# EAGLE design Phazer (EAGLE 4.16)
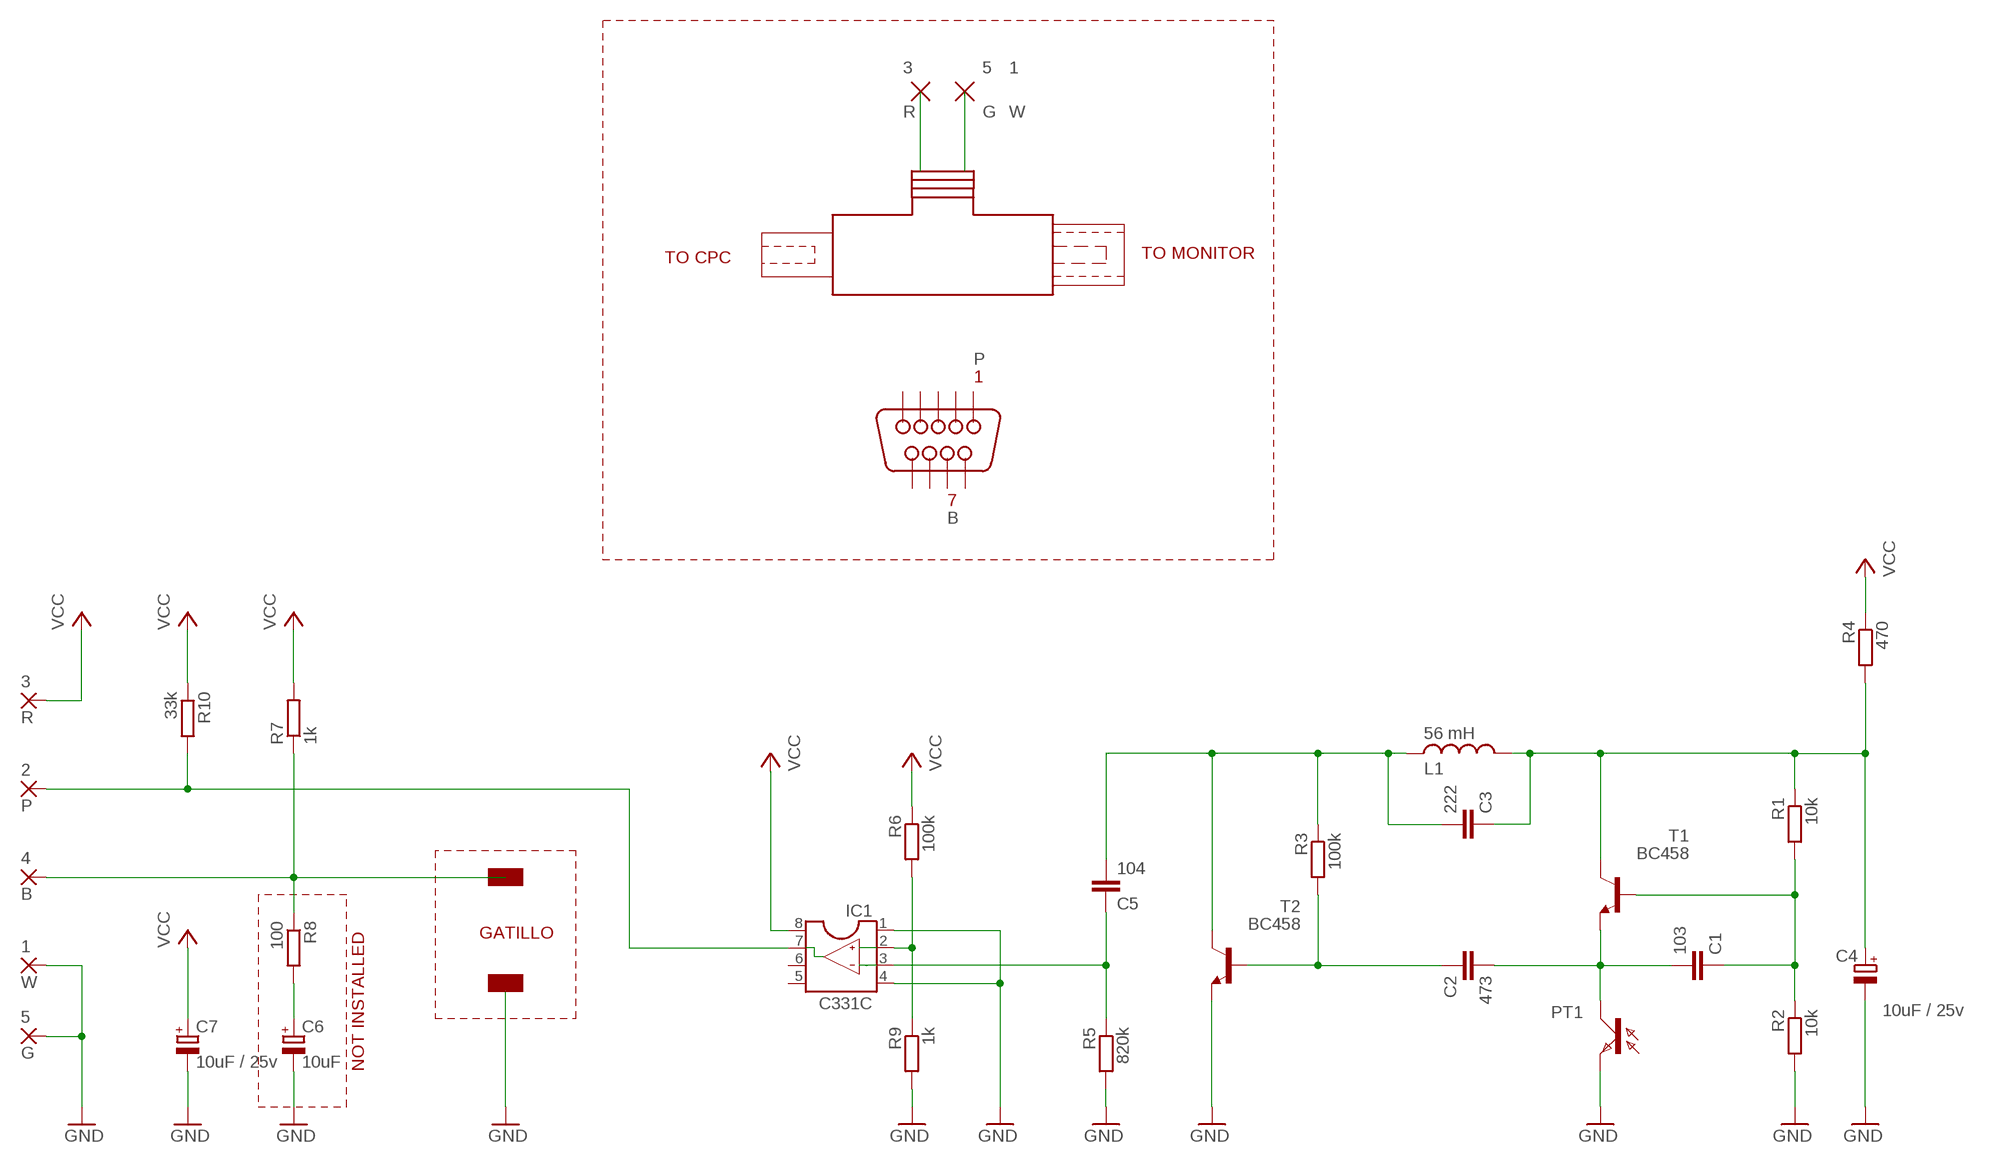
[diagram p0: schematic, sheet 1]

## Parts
1  W  SMD2  [SMD1,27-2,54]
2  P  SMD2  [SMD1,27-2,54]
3  R  SMD2  [SMD1,27-2,54]
4  B  SMD2  [SMD1,27-2,54]
5  G  SMD2  [SMD1,27-2,54]
C1  103  C-EU050-024X044  [C050-024X044]
C2  473  C-EU050-024X044  [C050-024X044]
C3  222  C-EU050-024X044  [C050-024X044]
C4  10uF / 25v  CPOL-EUE5-5  [E5-5]
C5  104  C-EU050-024X044  [C050-024X044]
C6  10uF  CPOL-EUE5-5  [E5-5]
C7  10uF / 25v  CPOL-EUE5-5  [E5-5]
IC1  C331C  DIL8  [DIL08]
L1  56 mH  L-US0204/5  [0204/5]
PT1  LPT80A  [LPT80A]
R1  10k  R-EU_0207/10  [0207/10]
R2  10k  R-EU_0207/10  [0207/10]
R3  100k  R-EU_0207/10  [0207/10]
R4  470  R-EU_0207/10  [0207/10]
R5  820k  R-EU_0207/10  [0207/10]
R6  100k  R-EU_0207/10  [0207/10]
R7  1k  R-EU_0207/10  [0207/10]
R8  100  R-EU_0207/10  [0207/10]
R9  1k  R-EU_0207/10  [0207/10]
R10  33k  R-EU_0207/10  [0207/10]
T1  BC458  BC368-NPN-TO92-BCE  [TO92-BCE]
T2  BC458  BC368-NPN-TO92-BCE  [TO92-BCE]

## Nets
GND: 1.1(P) 5.1(P) C4.- C6.- C7.- IC1.1 IC1.4 PT1.E R2.2 R5.2 R9.2 T2.E
N$1: C1.2 C2.2 PT1.C T1.E
N$2: C2.1 R3.2 T2.B
N$3: C1.1 R1.2 R2.1 T1.B
N$4: C3.1 C4.+ L1.1 R1.1 R4.2 T1.C
N$5: C3.2 C5.2 L1.2 R3.1 T2.C
N$6: 2.1(P) IC1.7 R10.2
N$7: C5.1 IC1.3 R5.1
N$8: C6.+ R8.2
N$12: IC1.2 R6.2 R9.1
N$13: 4.1(P) R7.1 R8.1
VCC: 3.1(P) C7.+ IC1.8 R4.1 R6.1 R7.2 R10.1
Unconnected: IC1.5 IC1.6

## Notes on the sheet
- 3 | 5 | 1
- R | G | W
- TO CPC | TO MONITOR
- P
- 1
- 7
- B
- GATILLO
- NOT INSTALLED

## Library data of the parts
1-5 = wirepad:SMD2: SMD PAD
C1-C3 C5 = rcl:C-EU: CAPACITOR, European symbol
C4 C6 C7 = rcl:CPOL-EU: POLARIZED CAPACITOR, European symbol
IC1 = ic-package:DIL8: Dual In Line
L1 = rcl:L-US: INDUCTOR, American symbol
PT1 = opto-trans-siemens:LPT80A: PHOTO TRANSISTOR
R1-R10 = rcl:R-EU_: RESISTOR, European symbol
T1 T2 = transistor:*-NPN-: NPN Transistror

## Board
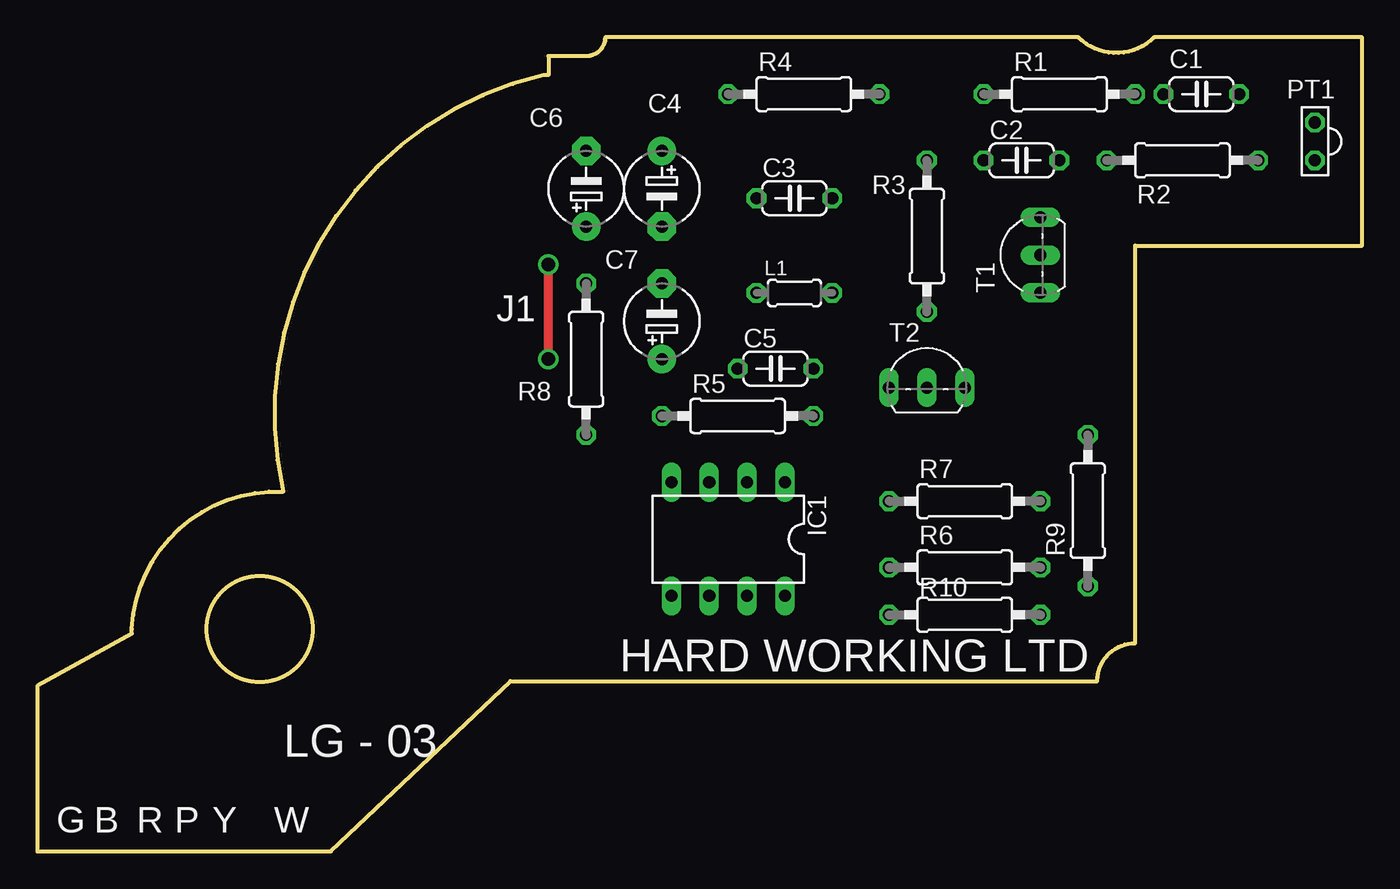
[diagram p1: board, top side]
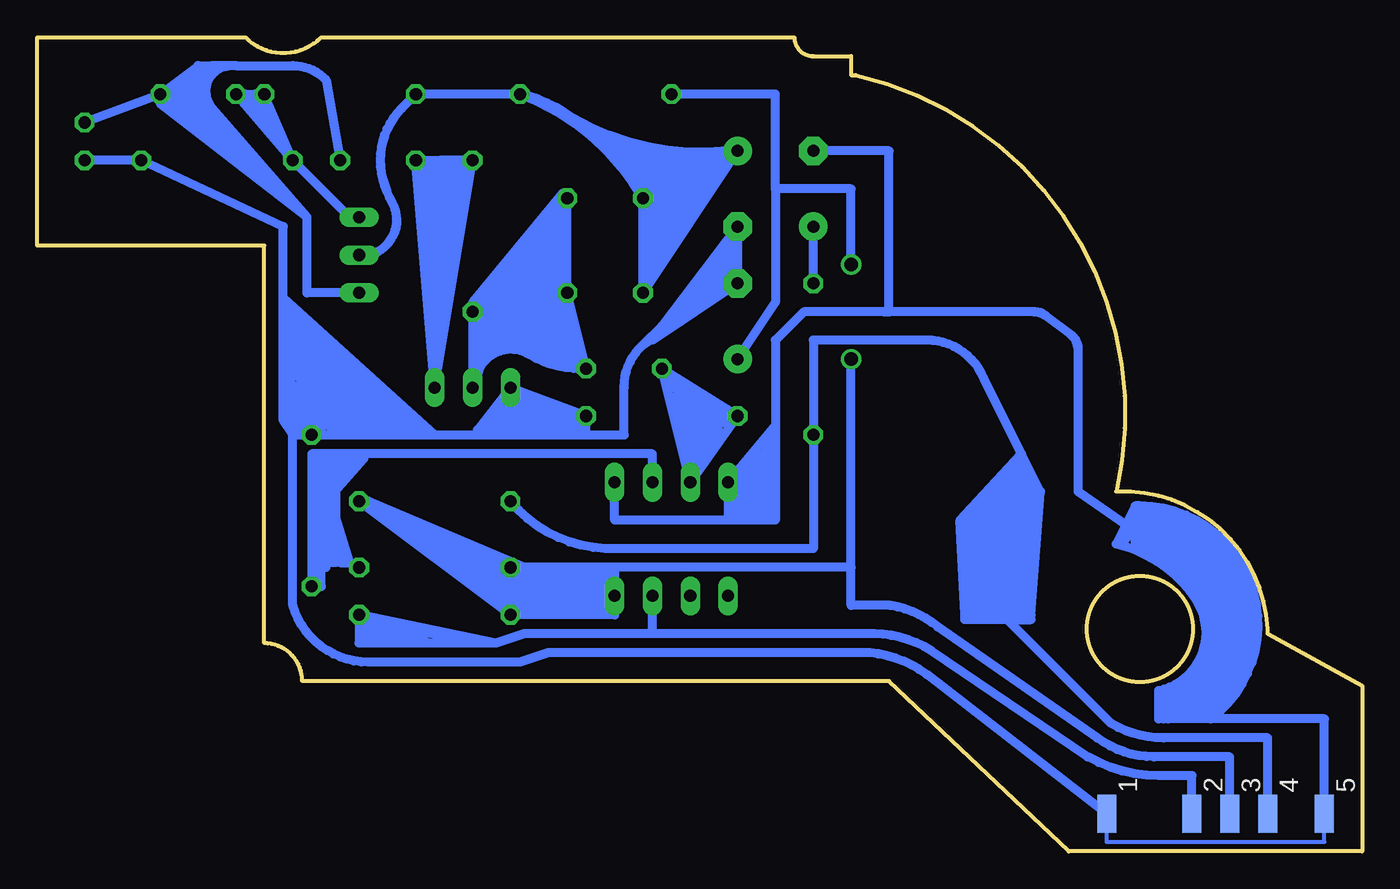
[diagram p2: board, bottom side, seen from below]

Size 88.9 x 54.61 mm. Coordinates in mm from the lower left corner, seen from the top.
Outline: 74.93,54.61 arc-90 69.85,54.61 38.1,54.61 arc-90 36.83,53.34 34.29,53.34 34.29,52.07 33.97,52.07 arc90 16.51,24.13 arc90 6.35,14.92 6.35,14.61 0,11.11 0,0 19.68,0 31.75,11.43 71.12,11.43 arc-90 73.66,13.97 73.66,40.64 88.9,40.64 88.9,54.61 74.93,54.61
Outline: circle at 14.92,14.92 radius 3.55
Copper layers (1*16): Top 0.035mm / dielectric 1.5mm / Bottom 0.035mm
Design rules "default": minimum track width 10mil, minimum drill 24mil, track to track 8mil, track to pad 8mil, pad to pad 8mil, via to via 8mil, smd to smd 8mil, copper to edge 40mil, drill to drill 8mil, minimum pad ring 10mil, minimum via ring 8mil, stop-mask expansion 4mil, vias tented up to drill 0mil, thermal gap 10mil

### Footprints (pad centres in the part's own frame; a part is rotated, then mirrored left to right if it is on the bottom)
SMD1,27-2,54 = smd 1.27 x 2.54: 1 0,0
C050-024X044 = drill 0.813 octagon: 1 -2.54,0; 2 2.54,0
E5-5 = drill 0.813 pad 1.905 round: + -2.54,0 | drill 0.813 pad 1.905 octagon: - 2.54,0
DIL08 = drill 0.813 long: 1 -3.81,-3.81; 2 -1.27,-3.81; 3 1.27,-3.81; 4 3.81,-3.81; 5 3.81,3.81; 6 1.27,3.81; 7 -1.27,3.81; 8 -3.81,3.81
0204/5 = drill 0.813 octagon: 1 -2.54,0; 2 2.54,0
LPT80A = drill 0.813 octagon: C 0,-1.27; E 0,1.27
0207/10 = drill 0.813 octagon: 1 -5.08,0; 2 5.08,0
TO92-BCE = drill 0.813 long: B 2.54,0; C 0,0; E -2.54,0

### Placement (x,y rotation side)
1  17.14,2.54 180 bottom
2  11.43,2.54 180 bottom
3  8.89,2.54 180 bottom
4  6.35,2.54 180 bottom
5  2.54,2.54 180 bottom
C1  78.11,50.8 0 top
C2  66.04,46.35 0 top
C3  50.8,43.81 0 top
C4  41.91,44.45 270 top
C5  49.53,32.38 0 top
C6  36.83,44.45 90 top
C7  41.91,35.56 90 top
IC1  46.35,20.95 180 top
L1  50.8,37.47 0 top
PT1  85.72,47.62 180 top
R1  68.58,50.8 0 top
R2  76.83,46.35 0 top
R3  59.69,41.27 90 top
R4  51.44,50.8 0 top
R5  46.99,29.21 0 top
R6  62.23,19.05 0 top
R7  62.23,23.5 0 top
R8  36.83,33.02 90 top
R9  70.48,22.86 90 top
R10  62.23,15.88 0 top
T1  67.31,40.01 90 top
T2  59.69,31.11 0 top

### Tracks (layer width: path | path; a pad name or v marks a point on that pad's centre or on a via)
GND
  Bottom 0.254: 5.1 2.54,0.64 17.14,0.64 1.1
  Bottom 0.61: PT1.E R2.2 72.39,41.91 72.39,37.15 | 1.1 29.22,11.88 arc-32 33.06,13.34 54.61,13.34 56.52,12.7 66.67,12.7 arc74 71.75,16.51 71.75,27.94 | 71.75,27.94 72.39,28.89 72.39,31.75 | 72.39,31.75 72.39,37.15 | 71.75,27.94 R9.2 68.58,27.94 | 68.58,27.94 62.23,27.94 | 62.23,27.94 52.07,27.94 | 52.07,27.94 52.07,28.89 | 52.07,28.89 R5.2 | 52.07,27.94 49.53,27.94 49.53,31.11 arc48 48.26,33.97 | 48.26,33.97 46.99,35.24 C4.- | 48.26,33.97 47.31,34.61 | R5.2 T2.E 59.37,28.26 52.39,28.26 52.39,28.57 58.74,28.57 58.42,28.89 52.07,28.89 | 52.07,28.89 53.02,29.21 58.42,29.21 57.78,29.53 53.98,29.53 54.93,29.84 57.78,29.84 57.47,30.16 55.56,30.16 57.15,30.48 R5.2 | 72.39,37.15 62.23,27.94 | 72.39,37.15 63.18,28.26 72.07,36.2 63.5,28.26 72.07,35.56 64.14,28.26 72.07,34.92 64.77,28.26 72.07,34.29 65.41,28.26 72.07,33.66 66.04,28.26 72.07,33.02 66.67,28.26 72.07,32.38 67.31,28.26 72.39,31.75 | 72.39,31.75 67.94,28.26 72.07,31.11 68.58,27.94 | 68.58,27.94 72.07,30.48 69.85,28.26 72.07,31.75 72.07,28.57 71.44,28.26 70.8,28.26 | 70.8,28.26 70.48,28.26 71.75,29.53 71.75,28.89 70.8,28.26 | C4.- C7.- 47.62,34.29 | C4.- 46.67,35.24 42.23,39.69 45.72,35.56 42.23,39.05 43.81,37.15 42.23,38.42 | C6.- 31.75,46.99 31.75,36.2 32.07,36.2 | 32.07,36.2 37.47,36.2 39.37,34.29 39.37,28.57 | 39.37,28.57 39.37,22.23 50.16,22.23 IC1.1 | 39.37,28.57 IC1.4 42.55,22.54 39.69,22.54 39.69,27.62 40.01,27.3 40.01,22.86 42.23,22.86 42.23,24.77 40.32,26.67 40.32,23.18 41.91,23.18 41.91,24.77 40.64,25.72 40.64,23.5 40.96,23.5 40.96,25.08 41.59,24.77 41.59,23.5 | 5.1 2.54,8.89 10.16,8.89 | 10.16,8.89 13.02,8.89
  Bottom 0.61: 13.02,8.89 13.34,8.89 | 13.34,8.89 13.65,8.89 13.65,10.79 arc-111 11.11,16.83 arc-44 16.51,20.64 15.88,21.91 | 15.88,21.91 15.24,23.18 14.92,23.18 arc143 10.16,8.89 | 32.07,36.2 22.01,36.2 arc37 21.25,35.94 19.56,34.67 arc53 19.05,33.66 19.05,24.13 15.88,21.91 | 13.34,8.89 13.34,10.48 12.7,10.79 13.02,8.89 | 13.02,8.89 12.38,10.79 12.38,9.21 12.06,11.11 12.06,9.21 11.75,11.43 11.75,9.21 11.43,11.75 11.43,9.21 11.11,12.38 11.11,9.21 10.79,13.02 10.79,9.21 10.48,13.02 | 10.48,13.02 10.48,9.21 | 10.48,13.02 10.48,21.27 10.16,20.95 10.16,9.21 9.84,9.53 9.84,20.95 9.53,20.64 9.53,9.84 9.21,10.16 9.21,20.32 8.89,19.68 8.89,10.79 8.57,11.11 8.57,19.37 8.26,18.73 8.26,11.75 7.94,12.38 7.94,18.1 7.62,17.14 7.62,13.02 10.79,16.83 10.79,21.59 11.11,21.91 11.11,17.14 11.75,18.1 11.43,18.1 11.43,21.91 11.75,22.23 11.75,18.41 12.06,18.41 12.06,22.23 12.38,22.23 12.38,18.73 12.7,19.05 12.7,22.54 13.02,22.54 13.02,19.37 13.34,19.68 13.34,22.54 13.65,22.54 13.65,19.68 13.97,20 13.97,22.86 14.29,22.86 14.29,20.32 14.61,20.32 14.61,22.86 14.92,22.86 14.92,20.32 15.24,20.64 15.24,22.54 15.88,20.95 | C4.- 44.45,37.78 42.55,40.01 C4.-
N$1
  Bottom 0.61: C1.2 PT1.C | C1.2 78.11,52.7 77.15,52.7 | 75.56,52.7 77.15,52.7 | 75.56,52.7 71.75,52.7 arc46 69.53,51.75 C2.2 | T1.E 70.8,37.47 70.8,42.55 | 70.8,42.55 80.64,50.16 C1.2 | 70.8,42.55 77.15,49.85 arc140 75.56,52.7 | 70.8,42.55 79.06,51.75 79.38,51.44 70.8,42.55 | 70.8,42.55 79.69,51.12 | 70.8,42.55 80.01,50.8 C1.2 | 70.8,42.55 C1.2 | 77.15,52.7 78.11,50.8 78.11,52.39 78.74,51.44 77.47,52.39
N$2
  Bottom 0.61: C2.1 T2.B R3.2 60.33,46.35 | 60.33,46.35 60.96,46.35 | 61.28,46.35 61.59,46.35 | 62.23,46.35 61.91,46.35 | 63.18,46.35 62.55,46.35 | C2.1 63.18,46.35 | 63.18,46.35 62.23,33.34 62.55,46.35 | 62.55,46.35 62.23,46.35 | 62.23,46.35 61.91,34.29 61.91,46.35 | 61.59,46.35 61.91,46.35 | 61.59,46.35 61.59,37.15 61.28,39.69 61.28,46.35 | 60.96,46.35 61.28,46.35 | 60.96,46.35 60.96,40.64 60.33,46.35 | 60.33,46.35 60.33,46.04 C2.1
N$3
  Bottom 0.61: R2.1 C1.1 74.93,50.8 | R2.1 R1.2 74.3,50.8 | 74.93,50.8 74.3,50.8 | R2.1 74.93,50.8 | R2.1 74.3,50.8 | R2.1 67.94,42.55 T1.B
N$4
  Bottom 0.61: T1.C arc-25 66.67,40.01 arc-106 65.09,43.5 arc13 65.72,45.09 arc60 64.45,49.85 R1.1 R4.2 | 42.55,46.99 arc37 53.02,49.21 arc-25 R4.2 | 42.23,46.99 C4.+ L1.1 48.26,38.1 | 42.55,46.99 42.23,46.99 | 48.26,38.1 48.26,40.01 | 48.26,40.64 48.26,41.59 | 48.26,41.59 C3.1 48.9,44.77 arc-36 R4.2 | 48.26,38.1 42.55,46.99 | 48.26,38.1 47.94,39.37 43.18,46.67 43.81,46.67 48.26,40.01 | 48.26,40.01 48.26,40.64 | 48.26,40.64 44.45,46.67 45.09,45.4 48.26,41.59 | 48.26,41.59 47.94,42.86 45.4,45.72 50.48,47.31 47.62,43.5 46.04,45.4 49.53,46.67 47.62,43.81 46.67,45.09 48.58,46.04 47.62,44.45 47.31,45.09 48.26,45.72 | 42.23,46.99 45.09,46.35 51.44,47.94 45.4,46.04
N$5
  Bottom 0.61: T2.C 59.37,32.07 arc103 55.88,33.34 arc-33 52.39,32.38 | 52.39,32.38 C5.2 L1.2 53.34,43.5 | 53.34,43.5 C3.2 R3.1 | R3.1 T2.C | R3.1 53.66,42.86 53.66,37.47 52.39,32.38 | 52.39,32.38 53.02,32.7 53.98,37.47 53.98,41.91 54.61,41.27 54.29,40.96 54.29,37.47 53.66,32.7 53.98,33.02 54.93,41.27 55.24,40.64 54.29,33.02 | T2.C 59.37,32.38 59.37,36.51 59.05,36.51 59.05,33.34 58.74,33.66 58.74,36.83 58.42,37.15 58.42,33.66 58.1,33.97 58.1,37.47 57.78,37.78 57.78,33.97 57.47,33.97 57.47,38.1 57.15,38.73 57.15,33.97 56.83,33.97 56.83,39.05 56.52,39.37 56.52,33.97 56.2,33.66 56.2,39.69 55.88,40.01 55.88,33.66 55.56,33.34 55.56,40.32 55.24,37.15 55.24,33.34 54.61,33.02 54.93,35.88 | R3.1 59.69,36.83 53.66,44.13 53.34,43.5
N$6
  Bottom 0.61: 2.1 11.43,5.08 13.65,5.08 arc30 18.41,6.35 28.9,13.46 arc-32 32.75,14.61 47.62,14.61 | 47.62,14.61 56.2,14.61 58.1,13.97 | 58.1,13.97 62.55,13.97 | 62.55,13.97 67.31,13.97 R10.2 | 58.1,13.97 R10.2 | 58.1,13.97 66.99,15.24 62.55,13.97 | 62.55,13.97 66.99,14.92 65.72,14.29 66.99,14.29 R10.2 | 47.62,14.61 IC1.7
N$7
  Bottom 0.61: C5.1 IC1.3 R5.1 C5.1 | C5.1 42.55,28.89 46.67,31.43 42.55,28.57 46.35,30.48 43.18,28.26 43.18,27.62 46.04,29.84 43.5,27.3 46.04,29.21 43.81,26.99 45.72,28.26 44.13,26.67 45.4,27.3 44.45,26.35 45.4,26.67 44.77,25.72 44.45,26.04
N$8
  Bottom 0.61: R8.2 C6.+
N$12
  Bottom 0.61: 68.9,26.67 47.62,26.67 IC1.2 | 68.9,26.67 69.85,26.67 | 70.17,26.67 70.48,26.67 R9.1 70.17,17.78 | 69.53,19.05 69.85,19.05 69.85,17.78 70.17,17.78 | 70.17,26.67 70.17,17.78 | 69.85,26.67 70.17,26.67 | 69.85,26.67 69.85,19.37 69.53,19.05 | 69.53,19.05 69.53,26.35 69.22,26.35 69.22,23.81 | 68.9,20.95 68.9,19.37 69.22,19.37 69.22,23.5 | 68.9,26.67 68.9,20.95 | 69.22,23.5 69.22,23.81 | 69.22,23.81 66.99,26.35 68.58,25.08 67.63,26.35 68.26,26.35 69.22,23.5 | 67.94,19.37 69.22,23.5 | 67.94,19.37 68.58,19.37 68.9,20.95 | R6.2 67.63,19.05 67.94,19.37
N$13
  Bottom 0.61: 4.1 6.35,7.62 13.34,7.62 arc31 16.83,8.57 23.81,15.56 | R7.1 arc-48 50.8,20.32 36.83,20.32 R8.1 36.83,34.29 29.21,34.29 arc67 25.4,31.75 22.86,26.67 | 23.81,15.56 22.23,15.56 22.23,15.88 | 22.23,15.88 21.59,24.13 22.86,26.67 | 22.86,26.67 26.99,22.23 26.67,15.88 22.23,15.88 | 23.81,15.56 26.67,15.56 26.67,22.23 26.35,22.54 26.35,16.19 26.04,16.19 | 26.04,16.19 25.72,16.19 | 26.04,16.19 26.04,22.86 25.72,23.18 25.72,16.19 | 25.72,16.19 25.4,16.19 25.4,23.5 25.08,23.81 25.08,16.19 24.77,16.19 24.77,24.13 24.45,24.45 24.45,16.19 24.13,16.19 24.13,24.45 23.81,25.08 23.81,16.19 23.5,16.19 23.5,25.4 23.18,25.72 23.18,16.19 22.86,16.19 22.86,26.04 22.54,25.08 22.54,24.77 | 22.54,24.77 22.54,16.19 21.91,24.13 22.54,24.77 | 22.54,24.77 22.23,23.81
VCC  (via drill 0.9)
  Top 0.61: v34.29,33.02 v34.29,39.37
  Bottom 0.61: R4.1 39.37,50.8 39.37,44.45 | 39.37,44.45 39.37,36.83 C7.+ | 39.37,44.45 34.29,44.45 v34.29,39.37 | R7.2 R6.1 56.2,19.05 | R7.2 R10.1 | R10.1 50.16,15.88 50.16,16.83 | R7.2 57.15,18.73 57.15,18.41 64.77,21.91 57.15,18.1 57.15,17.78 63.18,20.64 57.15,17.46 57.15,17.14 60.96,19.05 57.15,16.83 57.15,16.19 | 57.15,16.19 58.74,17.46 R10.1 | R10.1 57.15,16.19 | 57.15,16.19 50.48,16.19 50.48,16.51 56.83,16.51 56.83,16.83 50.16,16.83 | IC1.8 50.16,16.83 | IC1.8 56.83,17.14 56.83,17.46 50.16,17.46 50.16,17.78 56.83,17.78 56.83,18.1 50.16,18.1 50.16,18.41 57.47,18.41 57.47,18.73 50.16,18.73 50.16,19.05 | 50.16,19.05 56.2,19.05 | 50.16,19.05 IC1.8 | 34.29,19.05 50.16,19.05 | 34.29,19.05 v34.29,33.02 | 3.1 8.89,6.35 13.97,6.35 arc37 17.78,7.62 28.48,15.06 arc-31 31.68,16.51 34.29,16.51 34.29,19.05 | R7.2 66.67,23.5 56.2,19.05

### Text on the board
tPlace: J1 | HARD WORKING LTD | LG - 03 | G | B | R | P | Y | W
